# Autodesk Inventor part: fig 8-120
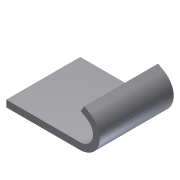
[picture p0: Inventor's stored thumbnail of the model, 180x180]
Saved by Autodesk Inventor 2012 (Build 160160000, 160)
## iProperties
Created: 2009-09
Part Number: fig 8-120
Document SubType Name: Modeling
Designer: Sham
Density: 1 g/cm^3
Material: Default
Author: Sham
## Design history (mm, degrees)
sketch "Sketch1"
  geometry: L1 (-33.976, 22)-(0, 22); L2 (0, 22)-(0, 0); L3 (0, 0)-(-33.976, 0); L4 (-33.976, 0)-(-33.976, 22)
  constraints: 8 end point, 2 parallel, 1 horizontal, 1 perpendicular
extrude "Extrusion1" new body sketch "Sketch1" distance "d0" = 2; taper "d1" = 0 deg
sketch "Sketch2"
  geometry: L1 (-12, 22)-(-12, 0)
  constraints: 2 end point
feature "Bend Part1" sketch "Sketch2" dims "d4" = 10, "d5" = 150 deg
body "Solid1"
